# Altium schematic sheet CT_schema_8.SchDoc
size 382 x 278 mm
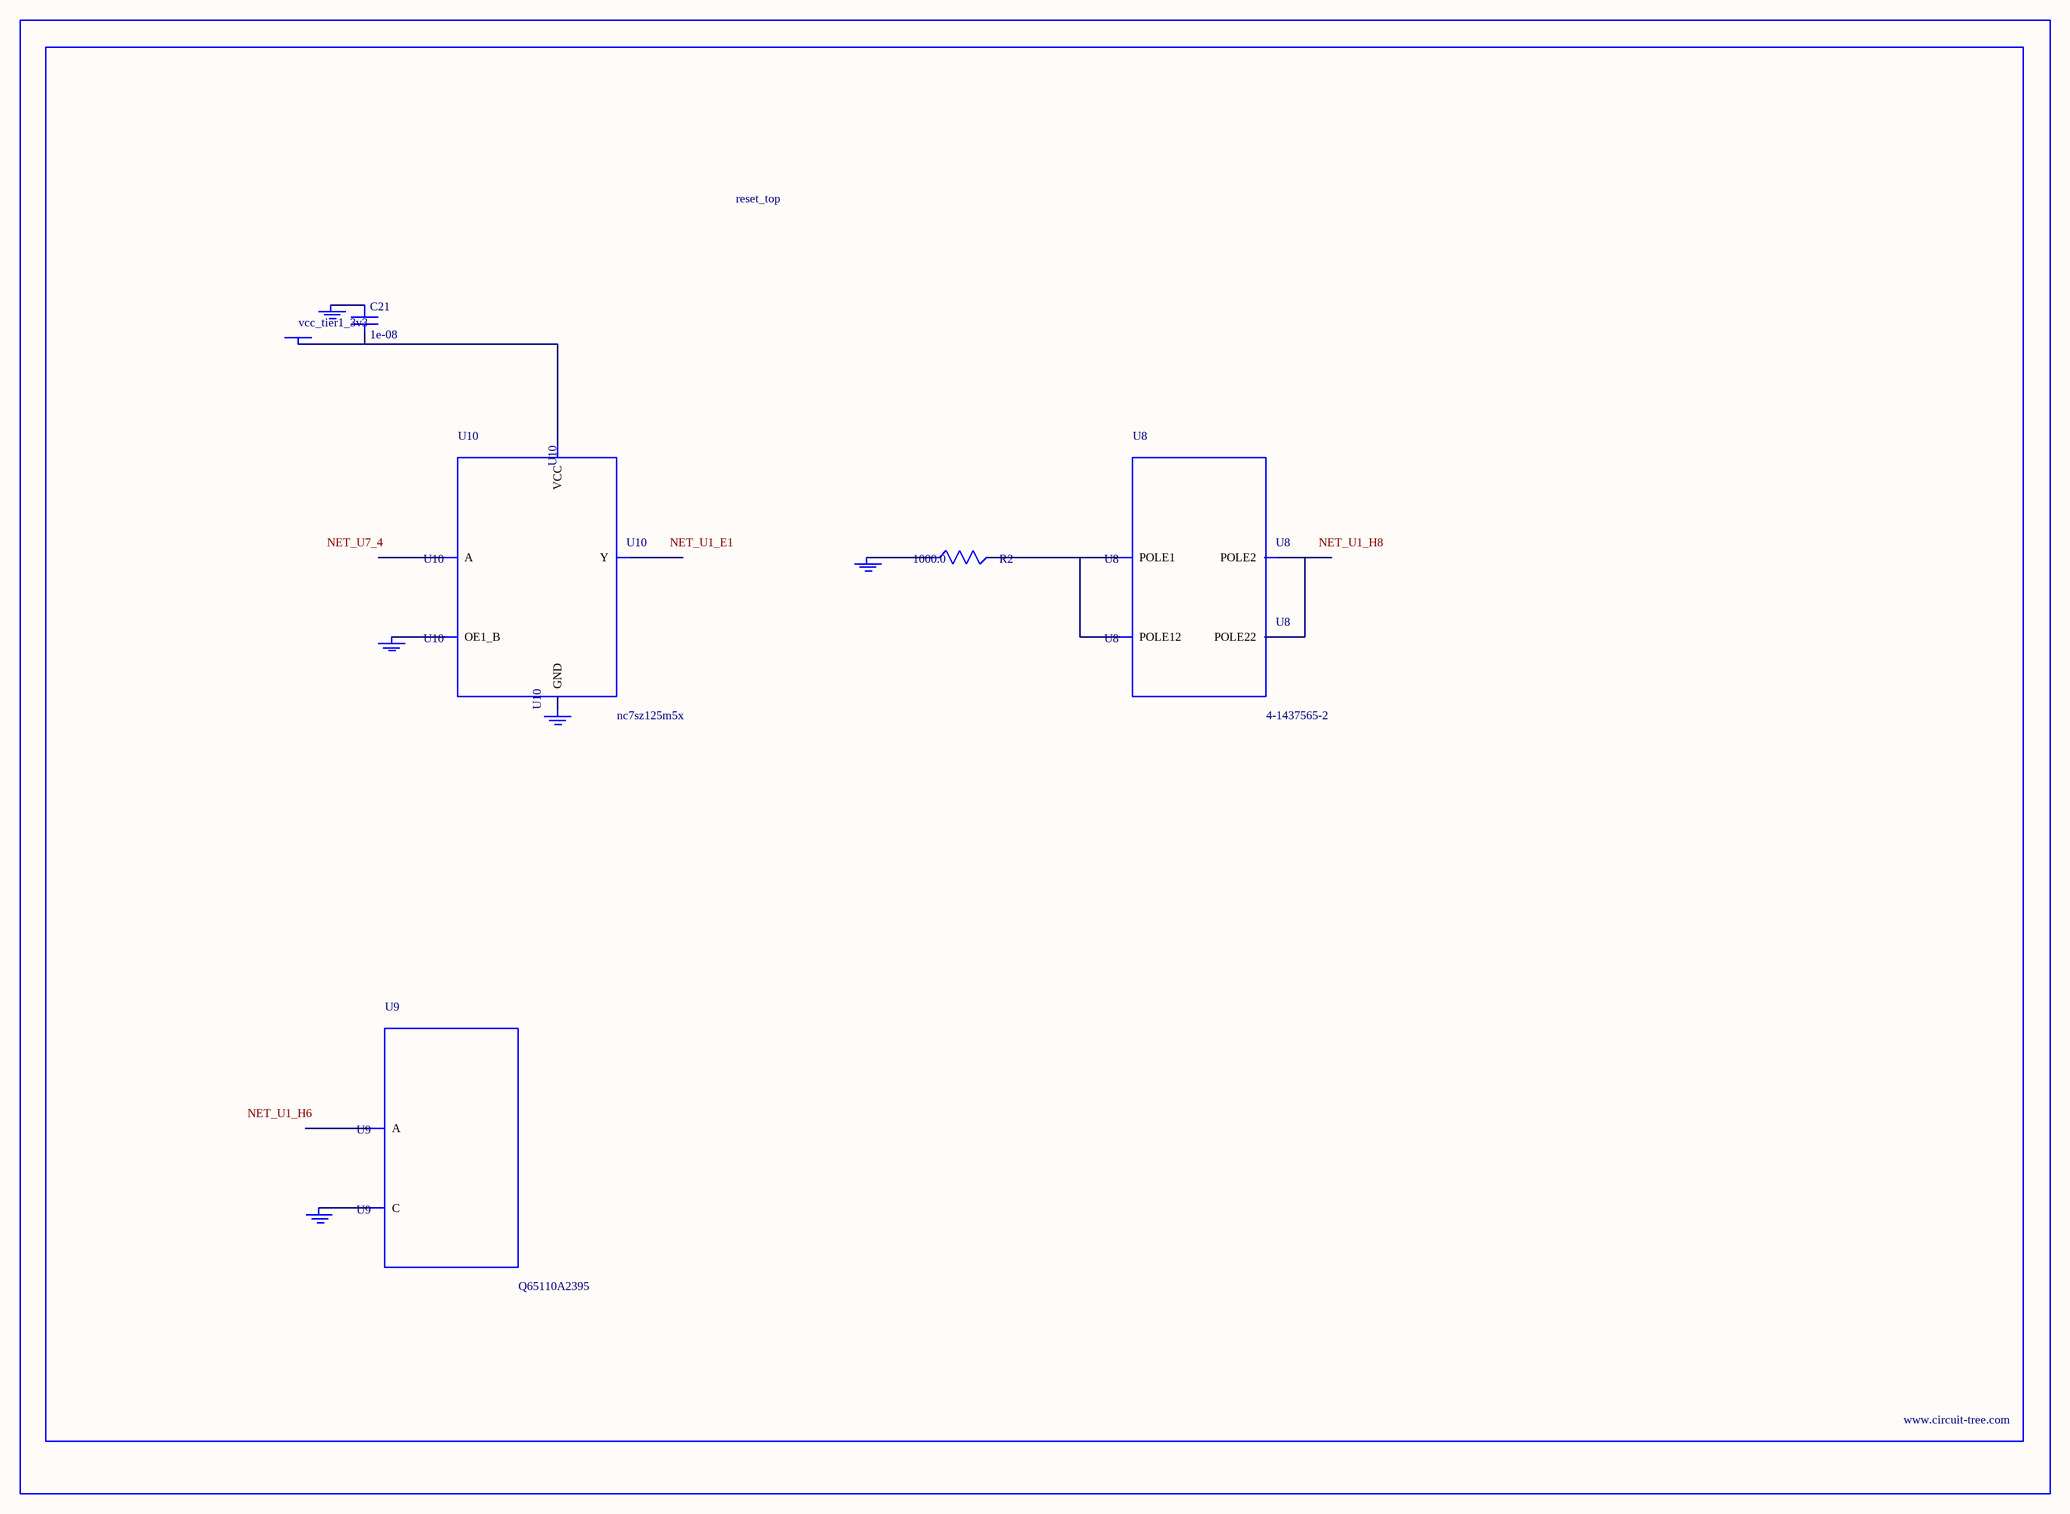
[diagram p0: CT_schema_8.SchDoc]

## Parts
BORDER7  (no value)
C21  1e-08  [C0402]
GND_INSTANCE_7_0  (no value)
GND_INSTANCE_7_1  (no value)
GND_INSTANCE_7_2  (no value)
GND_INSTANCE_7_3  (no value)
GND_INSTANCE_7_4  (no value)
POWER_INSTANCE_7_0  vcc_tier1_3v3
R2  1000.0  [R0603]
U8  4-1437565-2  [SW_4-1437565-2]
U9  Q65110A2395  [LGM67K-G1J2-24-Z]
U10  nc7sz125m5x  [NC7SZ125M5X]

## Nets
NetC21_1: C21.1 GND_INSTANCE_7_2.0(GND)
NetC21_2: C21.2 POWER_INSTANCE_7_0.0(PWR) U10.5(VCC)
NetGND_INSTANCE_7_0_0: GND_INSTANCE_7_0.0(GND) R2.1
NetGND_INSTANCE_7_1_0: GND_INSTANCE_7_1.0(GND) U9.C
NetGND_INSTANCE_7_3_0: GND_INSTANCE_7_3.0(GND) U10.1(OE1_B)
NetGND_INSTANCE_7_4_0: GND_INSTANCE_7_4.0(GND) U10.3(GND)
NetR2_2: R2.2 U8.1(POLE1) U8.2(POLE12)
NetU8_3: U8.3(POLE2) U8.4(POLE22)

Not connected (* = marked no-connect by the designer): U9 A; U10 2(A) 4(Y)

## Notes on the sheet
- Labels drawn without touching a wire or pin: NET_U1_E1, NET_U1_H6, NET_U1_H8, NET_U7_4

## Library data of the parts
BORDER7 = BORDER_PAGE7
C21 = C0402C103K3RAC
GND_INSTANCE_7_0-GND_INSTANCE_7_4 = GND
POWER_INSTANCE_7_0 = PWR
R2 = RC0603JR-071KL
